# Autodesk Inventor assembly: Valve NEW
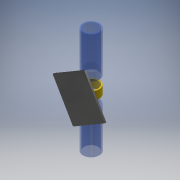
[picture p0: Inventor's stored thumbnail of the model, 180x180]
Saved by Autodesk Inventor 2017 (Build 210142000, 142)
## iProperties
Created: 2020-03
Part Number: Valve NEW
Description: STEP AP203
Document SubType Name: Assembly
Designer: user
Sending System: SolidWorks 2018
Preprocessor: SwSTEP 2.0
Title: Assem1.STEP
Revision Number: ANY
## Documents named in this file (8)
- C:\Users\user\Documents\Inventor\Home Ventilator CPAP\Valve NEW.iam
- C:\Users\user\Documents\Inventor\Home Ventilator CPAP\ball.ipt
- C:\Users\user\Documents\Inventor\Home Ventilator CPAP\bracket.ipt
- C:\Users\user\Documents\Inventor\Home Ventilator CPAP\rubber seal.ipt
- C:\Users\user\Documents\Inventor\Home Ventilator CPAP\Syringe.ipt
- C:\Users\user\Documents\Inventor\Home Ventilator CPAP\Tube.ipt
- C:\Users\user\Documents\Inventor\Home Ventilator CPAP\interrupt.ipt
- C:\Users\user\Documents\Inventor\Home Ventilator CPAP\Ring valve.ipt
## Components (8 placed, 8 different names)
1. ball_1
2. bracket_2
3. rubber seal_3
4. Syringe_4 — Mate:1
5. Tube_5 — Mate:2
6. Tube_6
7. interrupt_7
8. Ring valve:1 — Mate:1, Mate:2
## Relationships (2: Mate 2)
- Mate:1: Syringe_4 ↔ Ring valve:1
- Mate:2: Tube_5 ↔ Ring valve:1
